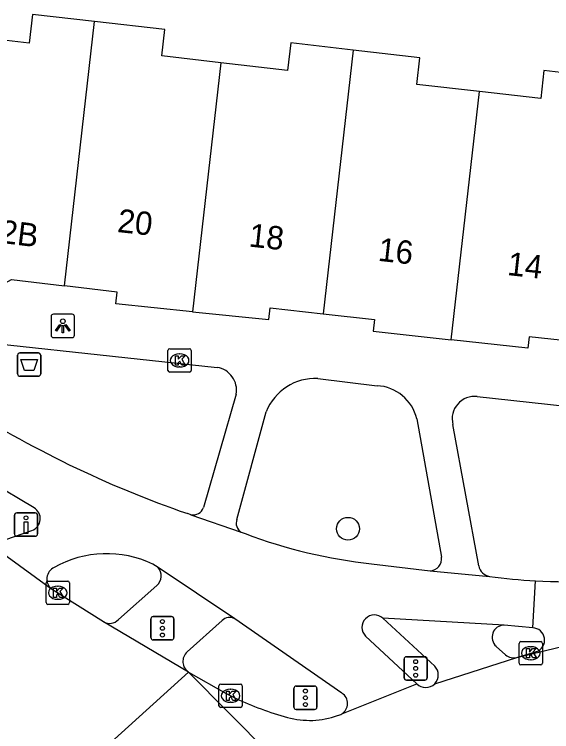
# Model space of a CAD drawing. Extents: x 160664 to 161506, y 382245 to 383288.
# Drawn here: x 160852.57 to 160875.62, y 382930.82 to 382961.58 of the extents above; entities that cross this region are included whole.
import ezdxf

# ---------------------------------------------------------------- set-up
doc = ezdxf.new("R2010")
doc.units = 0
for name, color, linetype in [('IMGEO_Afvalbak', 7, 'Continuous'), ('IMGEO_Boom', 7, 'Continuous'), ('IMGEO_Drukknoppaal', 7, 'Continuous'), ('IMGEO_Fietspad_gesloten', 7, 'Continuous'), ('IMGEO_Kolk', 7, 'Continuous'), ('IMGEO_Lichtpunt', 7, 'Continuous'), ('IMGEO_Pand', 7, 'Continuous'), ('IMGEO_Pand_nummerreeks', 7, 'Continuous'), ('IMGEO_Rijbaan_lokaal_gesloten', 7, 'Continuous'), ('IMGEO_Verkeersregelinstallatiepaal', 7, 'Continuous'), ('IMGEO_Voetpad_gesloten', 7, 'Continuous'), ('IMGEO_Voetpad_open', 7, 'Continuous')]:
    doc.layers.add(name, color=color, linetype=linetype)

msp = doc.modelspace()

# ---------------------------------------------------------------- linework, layer by layer
at = {"layer": 'IMGEO_Afvalbak'}
for p, q in [((160852.712, 382946.162), (160852.712, 382946.962)), ((160852.712, 382946.962), (160852.712, 382946.162)), ((160852.812, 382947.062), (160853.602, 382947.062)), ((160853.602, 382947.062), (160852.812, 382947.062)), ((160853.702, 382946.962), (160853.702, 382946.162)), ((160853.702, 382946.162), (160853.702, 382946.962)), ((160853.602, 382946.062), (160852.812, 382946.062)), ((160852.812, 382946.062), (160853.602, 382946.062))]:
    msp.add_line(p, q, dxfattribs=at)
msp.add_lwpolyline([(160852.855, 382946.776), (160853.559, 382946.776), (160853.41, 382946.306), (160853.004, 382946.306), (160852.855, 382946.776)], dxfattribs=at)
for centre, start, end in [((160852.812, 382946.962), 90, 180), ((160852.812, 382946.962), 90, 180), ((160853.602, 382946.962), 0, 90), ((160853.602, 382946.962), 360, 90), ((160852.812, 382946.162), 180, 270), ((160852.812, 382946.162), 180, 270), ((160853.602, 382946.162), 270, 0), ((160853.602, 382946.162), 270, 0)]:
    msp.add_arc(centre, 0.1, start, end, dxfattribs=at)
at = {"layer": 'IMGEO_Boom'}
msp.add_circle((160866.885, 382939.523), 0.489, dxfattribs=at)
at = {"layer": 'IMGEO_Drukknoppaal'}
for p, q in [((160852.677, 382940.201), (160853.467, 382940.201)), ((160853.467, 382940.201), (160852.677, 382940.201)), ((160852.577, 382939.301), (160852.577, 382940.101)), ((160852.577, 382940.101), (160852.577, 382939.301)), ((160853.567, 382940.101), (160853.567, 382939.301)), ((160853.567, 382939.301), (160853.567, 382940.101)), ((160853.467, 382939.201), (160852.677, 382939.201)), ((160852.677, 382939.201), (160853.467, 382939.201))]:
    msp.add_line(p, q, dxfattribs=at)
msp.add_lwpolyline([(160853.147, 382939.826), (160853.147, 382939.326), (160852.997, 382939.326), (160852.997, 382939.826), (160853.147, 382939.826)], dxfattribs=at)
msp.add_circle((160853.072, 382939.991), 0.085, dxfattribs=at)
for centre, start, end in [((160852.677, 382940.101), 90, 180), ((160852.677, 382940.101), 90, 180), ((160853.467, 382940.101), 0, 90), ((160853.467, 382940.101), 360, 90), ((160852.677, 382939.301), 180, 270), ((160852.677, 382939.301), 180, 270), ((160853.467, 382939.301), 270, 0), ((160853.467, 382939.301), 270, 0)]:
    msp.add_arc(centre, 0.1, start, end, dxfattribs=at)
at = {"layer": 'IMGEO_Fietspad_gesloten'}
for points in [[(160853.418, 382940.42), (160851.541, 382941.54)], [(160860.149, 382940.121), (160860.008, 382940.17)], [(160860.149, 382940.121), (160862.3, 382939.374)], [(160851.823, 382938.933), (160853.325, 382939.452)], [(160862.3, 382939.374), (160862.476, 382939.313)], [(160858.737, 382937.862), (160858.515, 382938.01)], [(160862.033, 382935.662), (160858.737, 382937.862)], [(160867.897, 382938.015), (160870.404, 382937.723)], [(160870.404, 382937.723), (160872.96, 382937.482)], [(160866.627, 382932.477), (160862.033, 382935.662)], [(160873.579, 382935.393), (160868.378, 382935.682)], [(160874.81, 382935.277), (160873.579, 382935.393)], [(160867.639, 382934.921), (160869.836, 382932.878)]]:
    msp.add_lwpolyline(points, dxfattribs=at)
for centre, radius, start, end in [((160874.969, 382983.557), 45.894, 237.2459, 250.9741), ((160853.15, 382939.957), 0.535, 289.1468, 59.8776), ((160870.371, 382960.315), 22.436, 249.3988, 263.6705), ((160856.541, 382933.82), 4.632, 64.7701, 119.2319), ((160854.521, 382937.365), 0.553, 115.9593, 230.3257), ((160876.352, 382962.177), 24.927, 262.1786, 266.7178), ((160868.014, 382935.297), 0.53, 46.6092, 225.0714), ((160866.33, 382932.033), 0.535, 302.2816, 56.1838)]:
    msp.add_arc(centre, radius, start, end, dxfattribs=at)
at = {"layer": 'IMGEO_Kolk'}
for p, q in [((160859.162, 382946.315), (160859.162, 382947.167)), ((160859.237, 382947.241), (160860.089, 382947.241)), ((160859.65, 382947.021), (160859.675, 382947.021)), ((160860.163, 382947.167), (160860.163, 382946.315)), ((160859.673, 382946.461), (160859.648, 382946.461)), ((160860.089, 382946.241), (160859.237, 382946.241)), ((160853.934, 382936.354), (160853.934, 382937.206)), ((160854.009, 382937.28), (160854.861, 382937.28)), ((160854.935, 382937.206), (160854.935, 382936.354)), ((160854.422, 382937.06), (160854.447, 382937.06)), ((160854.445, 382936.5), (160854.42, 382936.5)), ((160854.861, 382936.28), (160854.009, 382936.28)), ((160874.3, 382934.683), (160875.152, 382934.683)), ((160874.225, 382933.757), (160874.225, 382934.609)), ((160874.713, 382934.463), (160874.738, 382934.463)), ((160875.226, 382934.609), (160875.226, 382933.757)), ((160874.736, 382933.903), (160874.711, 382933.903)), ((160875.152, 382933.683), (160874.3, 382933.683)), ((160861.348, 382931.936), (160861.348, 382932.788)), ((160861.423, 382932.862), (160862.275, 382932.862)), ((160862.349, 382932.788), (160862.349, 382931.936)), ((160861.836, 382932.642), (160861.861, 382932.642)), ((160861.859, 382932.082), (160861.834, 382932.082)), ((160862.275, 382931.862), (160861.423, 382931.862))]:
    msp.add_line(p, q, dxfattribs=at)
for points in [[(160859.162, 382946.315), (160859.162, 382947.167)], [(160859.237, 382947.241), (160860.089, 382947.241)], [(160859.483, 382946.941), (160859.606, 382946.941), (160859.606, 382946.79), (160859.736, 382946.941), (160859.9, 382946.941), (160859.754, 382946.79), (160859.907, 382946.541), (160859.755, 382946.541), (160859.67, 382946.705), (160859.606, 382946.638), (160859.606, 382946.541), (160859.483, 382946.541), (160859.483, 382946.941)], [(160860.163, 382947.167), (160860.163, 382946.315)], [(160860.089, 382946.241), (160859.237, 382946.241)], [(160853.934, 382936.354), (160853.934, 382937.206)], [(160854.009, 382937.28), (160854.861, 382937.28)], [(160854.935, 382937.206), (160854.935, 382936.354)], [(160854.255, 382936.98), (160854.378, 382936.98), (160854.378, 382936.829), (160854.508, 382936.98), (160854.672, 382936.98), (160854.526, 382936.829), (160854.679, 382936.58), (160854.527, 382936.58), (160854.442, 382936.744), (160854.378, 382936.677), (160854.378, 382936.58), (160854.255, 382936.58), (160854.255, 382936.98)], [(160854.861, 382936.28), (160854.009, 382936.28)], [(160874.3, 382934.683), (160875.152, 382934.683)], [(160874.225, 382933.757), (160874.225, 382934.609)], [(160874.546, 382934.383), (160874.669, 382934.383), (160874.669, 382934.232), (160874.799, 382934.383), (160874.963, 382934.383), (160874.817, 382934.232), (160874.97, 382933.983), (160874.818, 382933.983), (160874.733, 382934.147), (160874.669, 382934.08), (160874.669, 382933.983), (160874.546, 382933.983), (160874.546, 382934.383)], [(160875.226, 382934.609), (160875.226, 382933.757)], [(160875.152, 382933.683), (160874.3, 382933.683)], [(160861.348, 382931.936), (160861.348, 382932.788)], [(160861.423, 382932.862), (160862.275, 382932.862)], [(160862.349, 382932.788), (160862.349, 382931.936)], [(160861.669, 382932.562), (160861.792, 382932.562), (160861.792, 382932.411), (160861.922, 382932.562), (160862.086, 382932.562), (160861.94, 382932.411), (160862.093, 382932.162), (160861.941, 382932.162), (160861.856, 382932.326), (160861.792, 382932.259), (160861.792, 382932.162), (160861.669, 382932.162), (160861.669, 382932.562)], [(160862.275, 382931.862), (160861.423, 382931.862)]]:
    msp.add_lwpolyline(points, dxfattribs=at)
for centre, start, end in [((160859.239, 382947.165), 91.552, 178.448), ((160859.239, 382947.165), 91.552, 178.448), ((160860.087, 382947.165), 1.552, 88.448), ((160860.087, 382947.165), 1.552, 88.448), ((160859.239, 382946.317), 181.552, 268.448), ((160859.239, 382946.317), 181.552, 268.448), ((160860.087, 382946.317), 271.552, 358.448), ((160860.087, 382946.317), 271.552, 358.448), ((160854.011, 382937.204), 91.552, 178.448), ((160854.011, 382937.204), 91.552, 178.448), ((160854.859, 382937.204), 1.552, 88.448), ((160854.859, 382937.204), 1.552, 88.448), ((160854.011, 382936.356), 181.552, 268.448), ((160854.011, 382936.356), 181.552, 268.448), ((160854.859, 382936.356), 271.552, 358.448), ((160854.859, 382936.356), 271.552, 358.448), ((160874.302, 382934.607), 91.552, 178.448), ((160874.302, 382934.607), 91.552, 178.448), ((160875.15, 382934.607), 1.552, 88.448), ((160875.15, 382934.607), 1.552, 88.448), ((160874.302, 382933.759), 181.552, 268.448), ((160874.302, 382933.759), 181.552, 268.448), ((160875.15, 382933.759), 271.552, 358.448), ((160875.15, 382933.759), 271.552, 358.448), ((160861.425, 382932.786), 91.552, 178.448), ((160861.425, 382932.786), 91.552, 178.448), ((160862.273, 382932.786), 1.552, 88.448), ((160862.273, 382932.786), 1.552, 88.448), ((160861.425, 382931.938), 181.552, 268.448), ((160861.425, 382931.938), 181.552, 268.448), ((160862.273, 382931.938), 271.552, 358.448), ((160862.273, 382931.938), 271.552, 358.448)]:
    msp.add_arc(centre, 0.0765, start, end, dxfattribs=at)
for centre, major_axis, ratio, start_param, end_param in [((160859.649, 382946.741), (-0.387, 0.002), 0.722429, 4.712389, 7.853982), ((160859.674, 382946.741), (-0.39, 0.002), 0.717154, 1.570796, 4.712389), ((160854.421, 382936.78), (-0.387, 0.002), 0.722429, 4.712389, 7.853982), ((160854.446, 382936.78), (-0.39, 0.002), 0.717154, 1.570796, 4.712389), ((160874.712, 382934.183), (-0.387, 0.002), 0.722429, 4.712389, 7.853982), ((160874.737, 382934.183), (-0.39, 0.002), 0.717154, 1.570796, 4.712389), ((160861.835, 382932.362), (-0.387, 0.002), 0.722429, 4.712389, 7.853982), ((160861.86, 382932.362), (-0.39, 0.002), 0.717154, 1.570796, 4.712389)]:
    msp.add_ellipse(centre, major_axis=major_axis, ratio=ratio, start_param=start_param, end_param=end_param, dxfattribs=at)
at = {"layer": 'IMGEO_Lichtpunt'}
for p, q in [((160854.152, 382948.624), (160854.152, 382947.817)), ((160854.152, 382948.624), (160854.152, 382947.817)), ((160855.054, 382948.719), (160854.246, 382948.719)), ((160855.054, 382948.719), (160854.246, 382948.719)), ((160855.148, 382947.817), (160855.148, 382948.624)), ((160855.148, 382947.817), (160855.148, 382948.624)), ((160854.246, 382947.723), (160855.054, 382947.723)), ((160854.246, 382947.723), (160855.054, 382947.723))]:
    msp.add_line(p, q, dxfattribs=at)
for points in [[(160854.526, 382948.288), (160854.565, 382948.26), (160854.377, 382947.998), (160854.339, 382948.025), (160854.526, 382948.288)], [(160854.628, 382948.24), (160854.675, 382948.24), (160854.675, 382947.918), (160854.628, 382947.918), (160854.628, 382948.24)], [(160854.738, 382948.26), (160854.776, 382948.287), (160854.963, 382948.025), (160854.924, 382947.997), (160854.738, 382948.26)]]:
    msp.add_lwpolyline(points, dxfattribs=at)
msp.add_circle((160854.651, 382948.422), 0.0994, dxfattribs=at)
for centre, start, end in [((160854.246, 382948.624), 90, 180), ((160854.246, 382948.624), 90, 180), ((160855.054, 382948.624), 0, 90), ((160855.054, 382948.624), 0, 90), ((160854.246, 382947.817), 180, 270), ((160854.246, 382947.817), 180, 270), ((160855.054, 382947.817), 270, 0), ((160855.054, 382947.817), 270, 360)]:
    msp.add_arc(centre, 0.0946, start, end, dxfattribs=at)
at = {"layer": 'IMGEO_Pand'}
for points in [[(160856.012, 382961.273), (160853.358, 382961.58), (160853.215, 382960.341), (160851.013, 382960.595), (160850.826, 382958.978), (160850.148, 382959.057)], [(160854.722, 382949.937), (160856.012, 382961.273)], [(160861.428, 382959.503), (160858.897, 382959.795), (160859.027, 382960.925), (160856.012, 382961.273)], [(160867.107, 382960.049), (160864.43, 382960.358), (160864.293, 382959.172), (160861.428, 382959.503)], [(160867.107, 382960.049), (160865.82, 382948.738)], [(160872.521, 382958.269), (160869.841, 382958.578), (160869.972, 382959.719), (160867.107, 382960.049)], [(160861.428, 382959.503), (160860.214, 382948.83)], [(160878.202, 382958.832), (160875.292, 382959.168), (160875.153, 382957.965), (160872.521, 382958.269)], [(160871.31, 382947.626), (160872.521, 382958.269)], [(160849.184, 382950.574), (160849.905, 382949.988), (160851.678, 382949.792), (160852.451, 382950.212), (160854.722, 382949.937)], [(160860.214, 382948.83), (160856.928, 382949.166), (160856.979, 382949.664), (160854.722, 382949.937)], [(160860.214, 382948.83), (160863.495, 382948.494), (160863.546, 382948.992), (160865.82, 382948.738)], [(160865.82, 382948.738), (160868.026, 382948.492), (160867.971, 382947.995), (160871.31, 382947.626)], [(160876.915, 382947.51), (160874.658, 382947.759), (160874.603, 382947.262), (160871.31, 382947.626)]]:
    msp.add_lwpolyline(points, dxfattribs=at)
at = {"layer": 'IMGEO_Rijbaan_lokaal_gesloten'}
for points in [[(160854.168, 382936.939), (160851.4, 382938.93)], [(160874.133, 382934.008), (160885.51, 382936.782), (160890.497, 382938.296), (160895.761, 382938.889), (160961.831, 382932.175), (160965.691, 382931.306), (160969.512, 382929.861), (160972.821, 382927.904), (160976.623, 382925.025), (160978.469, 382923.697)], [(160874.81, 382935.277), (160874.925, 382937.291)], [(160856.4, 382935.532), (160854.168, 382936.939)], [(160860.049, 382933.373), (160856.4, 382935.532)], [(160874.133, 382934.008), (160874.967, 382934.253)], [(160870.606, 382932.878), (160874.133, 382934.008)], [(160860.049, 382933.373), (160856.414, 382930.084), (160856.414, 382930.084)], [(160870.47, 382922.866), (160860.049, 382933.373)], [(160860.049, 382933.373), (160861.66, 382932.461), (160862.06, 382932.256)], [(160866.615, 382931.581), (160869.836, 382932.878)]]:
    msp.add_lwpolyline(points, dxfattribs=at)
for centre, radius, start, end in [((160876.344, 382962.262), 25.011, 266.7469, 278.5089), ((160874.791, 382934.75), 0.527, 289.5238, 87.9097), ((160870.221, 382933.251), 0.536, 224.1067, 315.8933), ((160867.801, 382944.418), 13.449, 244.7324, 254.8774), ((160866.32, 382932.059), 0.561, 282.2383, 301.7009), ((160865.247, 382934.872), 3.567, 254.4733, 289.5281)]:
    msp.add_arc(centre, radius, start, end, dxfattribs=at)
at = {"layer": 'IMGEO_Verkeersregelinstallatiepaal'}
for p, q in [((160858.43, 382934.855), (160858.43, 382935.655)), ((160858.43, 382935.655), (160858.43, 382934.855)), ((160858.53, 382935.755), (160859.32, 382935.755)), ((160859.32, 382935.755), (160858.53, 382935.755)), ((160859.42, 382935.655), (160859.42, 382934.855)), ((160859.42, 382934.855), (160859.42, 382935.655)), ((160859.32, 382934.755), (160858.53, 382934.755)), ((160858.53, 382934.755), (160859.32, 382934.755)), ((160869.392, 382934.034), (160870.182, 382934.034)), ((160870.182, 382934.034), (160869.392, 382934.034)), ((160869.292, 382933.134), (160869.292, 382933.934)), ((160869.292, 382933.934), (160869.292, 382933.134)), ((160870.282, 382933.934), (160870.282, 382933.134)), ((160870.282, 382933.134), (160870.282, 382933.934)), ((160870.182, 382933.034), (160869.392, 382933.034)), ((160869.392, 382933.034), (160870.182, 382933.034)), ((160864.563, 382931.875), (160864.563, 382932.675)), ((160864.563, 382932.675), (160864.563, 382931.875)), ((160864.663, 382932.775), (160865.453, 382932.775)), ((160865.453, 382932.775), (160864.663, 382932.775)), ((160865.553, 382932.675), (160865.553, 382931.875)), ((160865.553, 382931.875), (160865.553, 382932.675)), ((160865.453, 382931.775), (160864.663, 382931.775)), ((160864.663, 382931.775), (160865.453, 382931.775))]:
    msp.add_line(p, q, dxfattribs=at)
for centre in [(160858.925, 382935.545), (160858.925, 382935.255), (160858.925, 382934.965), (160869.787, 382933.824), (160869.787, 382933.534), (160869.787, 382933.244), (160865.058, 382932.565), (160865.058, 382932.275), (160865.058, 382931.985)]:
    msp.add_circle(centre, 0.085, dxfattribs=at)
for centre, start, end in [((160858.53, 382935.655), 90, 180), ((160858.53, 382935.655), 90, 180), ((160859.32, 382935.655), 0, 90), ((160859.32, 382935.655), 360, 90), ((160858.53, 382934.855), 180, 270), ((160858.53, 382934.855), 180, 270), ((160859.32, 382934.855), 270, 0), ((160859.32, 382934.855), 270, 0), ((160869.392, 382933.934), 90, 180), ((160869.392, 382933.934), 90, 180), ((160870.182, 382933.934), 0, 90), ((160870.182, 382933.934), 360, 90), ((160869.392, 382933.134), 180, 270), ((160869.392, 382933.134), 180, 270), ((160870.182, 382933.134), 270, 0), ((160870.182, 382933.134), 270, 0), ((160864.663, 382932.675), 90, 180), ((160864.663, 382932.675), 90, 180), ((160865.453, 382932.675), 0, 90), ((160865.453, 382932.675), 360, 90), ((160864.663, 382931.875), 180, 270), ((160864.663, 382931.875), 180, 270), ((160865.453, 382931.875), 270, 0), ((160865.453, 382931.875), 270, 0)]:
    msp.add_arc(centre, 0.1, start, end, dxfattribs=at)
at = {"layer": 'IMGEO_Voetpad_gesloten'}
for points in [[(160857.037, 382935.629), (160858.678, 382937.091)], [(160861.485, 382935.587), (160859.985, 382934.241)], [(160870.603, 382933.629), (160868.378, 382935.682)], [(160873.246, 382934.481), (160873.646, 382934.113)]]:
    msp.add_lwpolyline(points, dxfattribs=at)
for centre, radius, start, end in [((160858.338, 382937.505), 0.536, 309.408, 41.84), ((160856.656, 382935.989), 0.524, 240.7208, 316.5958), ((160861.811, 382935.245), 0.473, 61.9987, 133.5876), ((160873.586, 382934.874), 0.519, 90.7446, 229.1379), ((160860.35, 382933.832), 0.549, 131.7188, 236.7151), ((160873.993, 382934.538), 0.549, 230.8251, 284.8408), ((160870.222, 382933.252), 0.536, 315.7607, 44.6971)]:
    msp.add_arc(centre, radius, start, end, dxfattribs=at)
at = {"layer": 'IMGEO_Voetpad_open'}
for points in [[(160847.266, 382947.954), (160861.276, 382946.44)], [(160865.592, 382945.964), (160868.13, 382945.657)], [(160862.089, 382945.295), (160860.685, 382940.431)], [(160872.431, 382945.192), (160891.701, 382943.093), (160891.553, 382941.627)], [(160862.122, 382939.917), (160863.38, 382944.541)], [(160869.841, 382944.236), (160870.891, 382938.311)], [(160872.491, 382937.932), (160871.383, 382943.996)]]:
    msp.add_lwpolyline(points, dxfattribs=at)
for centre, radius, start, end in [((160861.111, 382945.462), 0.992, 350.3254, 80.4275), ((160865.478, 382943.711), 2.256, 87.1028, 158.4043), ((160868.024, 382943.789), 1.871, 13.8205, 86.7597), ((160872.317, 382944.235), 0.964, 83.2183, 194.3285), ((160860.236, 382940.59), 0.477, 259.5365, 340.5501), ((160862.526, 382939.749), 0.438, 157.4051, 238.894), ((160870.393, 382938.228), 0.505, 271.2637, 9.4711), ((160873.048, 382938.043), 0.568, 191.2681, 261.1007)]:
    msp.add_arc(centre, radius, start, end, dxfattribs=at)

# ---------------------------------------------------------------- texts
at = {"layer": 'IMGEO_Pand_nummerreeks'}
for s, rotation, p in [('22-22B', 353.0959, (160849.26, 382952.109)), ('20', 353.7001, (160856.962, 382952.25)), ('18', 353.7001, (160862.6, 382951.628)), ('16', 353.7001, (160868.143, 382951.016)), ('14', 353.7001, (160873.69, 382950.404))]:
    msp.add_text(s, height=1, rotation=rotation, dxfattribs=at).set_placement(p)

doc.saveas('drawing.dxf')
